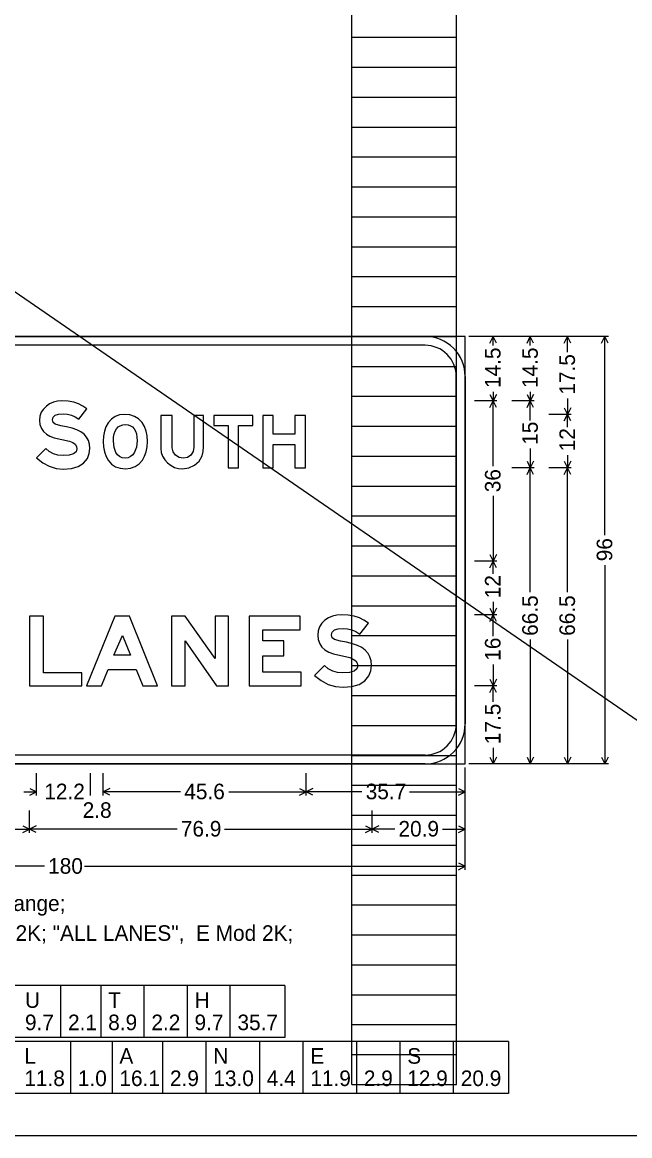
# Model space of a CAD drawing. Extents: x 1820207 to 1820557, y 740216 to 740315.
# Drawn here: x 1820495.55 to 1820501.23, y 740293.6 to 740304.02 of the extents above; entities that cross this region are included whole.
import ezdxf

# ---------------------------------------------------------------- set-up
doc = ezdxf.new("R2010")
doc.units = 0
for name, color, linetype in [('SC_Scratch1', 7, 'Continuous'), ('SC_Scratch2', 7, 'Continuous'), ('SC_Scratch3', 7, 'Continuous'), ('SC_Shading1', 7, 'Continuous')]:
    doc.layers.add(name, color=color, linetype=linetype)

msp = doc.modelspace()

# ---------------------------------------------------------------- linework, layer by layer
at = {"layer": 'SC_Scratch1'}
for p, q in [((1820498.631, 740294.081), (1820498.631, 740314.241)), ((1820499.611, 740294.081), (1820499.611, 740314.241)), ((1820498.631, 740303.881), (1820499.611, 740303.881)), ((1820498.631, 740303.601), (1820499.611, 740303.601)), ((1820498.631, 740303.321), (1820499.611, 740303.321)), ((1820498.631, 740303.041), (1820499.611, 740303.041)), ((1820498.631, 740302.761), (1820499.611, 740302.761)), ((1820498.631, 740302.481), (1820499.611, 740302.481)), ((1820498.631, 740302.201), (1820499.611, 740302.201)), ((1820498.631, 740301.921), (1820499.611, 740301.921)), ((1820498.631, 740301.641), (1820499.611, 740301.641)), ((1820498.631, 740301.361), (1820499.611, 740301.361)), ((1820498.631, 740301.081), (1820499.611, 740301.081)), ((1820498.631, 740300.801), (1820499.611, 740300.801)), ((1820498.631, 740300.521), (1820499.611, 740300.521)), ((1820498.631, 740300.241), (1820499.611, 740300.241)), ((1820498.631, 740299.961), (1820499.611, 740299.961)), ((1820498.631, 740299.681), (1820499.611, 740299.681)), ((1820498.631, 740299.401), (1820499.611, 740299.401)), ((1820498.631, 740299.121), (1820499.611, 740299.121)), ((1820498.631, 740298.841), (1820499.611, 740298.841)), ((1820498.631, 740298.561), (1820499.611, 740298.561)), ((1820498.631, 740298.281), (1820499.611, 740298.281)), ((1820498.631, 740298.001), (1820499.611, 740298.001)), ((1820498.631, 740297.721), (1820499.611, 740297.721)), ((1820498.631, 740297.441), (1820499.611, 740297.441)), ((1820498.631, 740297.161), (1820499.611, 740297.161)), ((1820498.631, 740296.881), (1820499.611, 740296.881)), ((1820498.631, 740296.601), (1820499.611, 740296.601)), ((1820498.631, 740296.321), (1820499.611, 740296.321)), ((1820498.631, 740296.041), (1820499.611, 740296.041)), ((1820498.631, 740295.761), (1820499.611, 740295.761)), ((1820498.631, 740295.481), (1820499.611, 740295.481)), ((1820498.631, 740295.201), (1820499.611, 740295.201)), ((1820498.631, 740294.921), (1820499.611, 740294.921)), ((1820498.631, 740294.641), (1820499.611, 740294.641)), ((1820498.631, 740294.361), (1820499.611, 740294.361)), ((1820498.631, 740294.081), (1820499.611, 740294.081))]:
    msp.add_line(p, q, dxfattribs=at)
at = {"layer": 'SC_Scratch2'}
msp.add_lwpolyline([(1820476.451, 740314.601), (1820506.951, 740314.601), (1820506.951, 740293.601), (1820476.451, 740293.601)], close=True, dxfattribs=at)
at = {"layer": 'SC_Scratch3'}
for p, q in [((1820501.033, 740301.081), (1820499.726, 740301.081)), ((1820499.987, 740301.081), (1820499.778, 740301.081)), ((1820499.921, 740301.019), (1820499.952, 740301.081)), ((1820499.952, 740300.995), (1820499.952, 740301.081)), ((1820499.984, 740301.019), (1820499.952, 740301.081)), ((1820500.336, 740301.081), (1820500.127, 740301.081)), ((1820500.27, 740301.019), (1820500.301, 740301.081)), ((1820500.301, 740300.995), (1820500.301, 740301.081)), ((1820500.332, 740301.019), (1820500.301, 740301.081)), ((1820500.684, 740301.081), (1820500.475, 740301.081)), ((1820500.618, 740301.019), (1820500.65, 740301.081)), ((1820500.65, 740300.933), (1820500.65, 740301.081)), ((1820500.681, 740301.019), (1820500.65, 740301.081)), ((1820500.967, 740301.019), (1820500.998, 740301.081)), ((1820500.998, 740299.22), (1820500.998, 740301.081)), ((1820501.029, 740301.019), (1820500.998, 740301.081)), ((1820499.987, 740300.477), (1820499.778, 740300.477)), ((1820499.921, 740300.539), (1820499.952, 740300.477)), ((1820499.921, 740300.415), (1820499.952, 740300.477)), ((1820499.952, 740300.563), (1820499.952, 740300.477)), ((1820499.984, 740300.539), (1820499.952, 740300.477)), ((1820499.952, 740299.866), (1820499.952, 740300.477)), ((1820499.984, 740300.415), (1820499.952, 740300.477)), ((1820500.336, 740300.477), (1820500.127, 740300.477)), ((1820500.27, 740300.539), (1820500.301, 740300.477)), ((1820500.27, 740300.415), (1820500.301, 740300.477)), ((1820500.301, 740300.563), (1820500.301, 740300.477)), ((1820500.332, 740300.539), (1820500.301, 740300.477)), ((1820500.301, 740300.296), (1820500.301, 740300.477)), ((1820500.332, 740300.415), (1820500.301, 740300.477)), ((1820500.65, 740300.501), (1820500.65, 740300.352)), ((1820500.618, 740300.414), (1820500.65, 740300.352)), ((1820500.681, 740300.414), (1820500.65, 740300.352)), ((1820500.684, 740300.352), (1820500.475, 740300.352)), ((1820500.618, 740300.29), (1820500.65, 740300.352)), ((1820500.65, 740300.233), (1820500.65, 740300.352)), ((1820500.681, 740300.29), (1820500.65, 740300.352)), ((1820500.301, 740300.033), (1820500.301, 740299.852)), ((1820500.65, 740299.971), (1820500.65, 740299.852)), ((1820500.336, 740299.852), (1820500.127, 740299.852)), ((1820500.336, 740299.852), (1820500.127, 740299.852)), ((1820500.27, 740299.914), (1820500.301, 740299.852)), ((1820500.27, 740299.79), (1820500.301, 740299.852)), ((1820500.332, 740299.914), (1820500.301, 740299.852)), ((1820500.301, 740298.689), (1820500.301, 740299.852)), ((1820500.332, 740299.79), (1820500.301, 740299.852)), ((1820500.684, 740299.852), (1820500.475, 740299.852)), ((1820500.684, 740299.852), (1820500.475, 740299.852)), ((1820500.618, 740299.914), (1820500.65, 740299.852)), ((1820500.618, 740299.79), (1820500.65, 740299.852)), ((1820500.681, 740299.914), (1820500.65, 740299.852)), ((1820500.65, 740298.689), (1820500.65, 740299.852)), ((1820500.681, 740299.79), (1820500.65, 740299.852)), ((1820499.952, 740299.588), (1820499.952, 740298.977)), ((1820499.921, 740299.039), (1820499.952, 740298.977)), ((1820499.984, 740299.039), (1820499.952, 740298.977)), ((1820499.987, 740298.977), (1820499.778, 740298.977)), ((1820499.921, 740298.915), (1820499.952, 740298.977)), ((1820499.952, 740298.858), (1820499.952, 740298.977)), ((1820499.984, 740298.915), (1820499.952, 740298.977)), ((1820500.998, 740298.942), (1820500.998, 740297.081)), ((1820499.952, 740298.596), (1820499.952, 740298.477)), ((1820499.921, 740298.539), (1820499.952, 740298.477)), ((1820499.984, 740298.539), (1820499.952, 740298.477)), ((1820499.987, 740298.477), (1820499.778, 740298.477)), ((1820499.921, 740298.415), (1820499.952, 740298.477)), ((1820499.952, 740298.276), (1820499.952, 740298.477)), ((1820499.984, 740298.415), (1820499.952, 740298.477)), ((1820500.301, 740298.244), (1820500.301, 740297.081)), ((1820500.65, 740298.244), (1820500.65, 740297.081)), ((1820499.952, 740298.011), (1820499.952, 740297.81)), ((1820499.921, 740297.873), (1820499.952, 740297.81)), ((1820499.984, 740297.873), (1820499.952, 740297.81)), ((1820499.987, 740297.81), (1820499.778, 740297.81)), ((1820499.987, 740297.81), (1820499.778, 740297.81)), ((1820499.921, 740297.748), (1820499.952, 740297.81)), ((1820499.952, 740297.662), (1820499.952, 740297.81)), ((1820499.984, 740297.748), (1820499.952, 740297.81)), ((1820499.921, 740297.144), (1820499.952, 740297.081)), ((1820499.952, 740297.23), (1820499.952, 740297.081)), ((1820499.984, 740297.144), (1820499.952, 740297.081)), ((1820500.27, 740297.144), (1820500.301, 740297.081)), ((1820500.332, 740297.144), (1820500.301, 740297.081)), ((1820500.618, 740297.144), (1820500.65, 740297.081)), ((1820500.681, 740297.144), (1820500.65, 740297.081)), ((1820500.967, 740297.144), (1820500.998, 740297.081)), ((1820501.029, 740297.144), (1820500.998, 740297.081)), ((1820499.691, 740296.088), (1820499.691, 740297.046)), ((1820501.033, 740297.081), (1820499.726, 740297.081)), ((1820499.987, 740297.081), (1820499.778, 740297.081)), ((1820500.336, 740297.081), (1820500.127, 740297.081)), ((1820500.684, 740297.081), (1820500.475, 740297.081)), ((1820495.679, 740296.785), (1820495.679, 740296.994)), ((1820496.185, 740296.785), (1820496.185, 740296.994)), ((1820496.303, 740296.785), (1820496.303, 740296.994)), ((1820498.203, 740296.785), (1820498.203, 740296.994)), ((1820498.203, 740296.785), (1820498.203, 740296.994)), ((1820499.691, 740296.785), (1820499.691, 740296.994)), ((1820495.56, 740296.82), (1820495.679, 740296.82)), ((1820495.616, 740296.851), (1820495.679, 740296.82)), ((1820495.616, 740296.789), (1820495.679, 740296.82)), ((1820496.365, 740296.851), (1820496.303, 740296.82)), ((1820497.027, 740296.82), (1820496.303, 740296.82)), ((1820496.365, 740296.789), (1820496.303, 740296.82)), ((1820497.479, 740296.82), (1820498.203, 740296.82)), ((1820498.141, 740296.851), (1820498.203, 740296.82)), ((1820498.141, 740296.789), (1820498.203, 740296.82)), ((1820498.265, 740296.851), (1820498.203, 740296.82)), ((1820498.725, 740296.82), (1820498.203, 740296.82)), ((1820498.265, 740296.789), (1820498.203, 740296.82)), ((1820499.169, 740296.82), (1820499.691, 740296.82)), ((1820499.629, 740296.851), (1820499.691, 740296.82)), ((1820499.629, 740296.789), (1820499.691, 740296.82)), ((1820495.614, 740296.436), (1820495.614, 740296.645)), ((1820498.821, 740296.436), (1820498.821, 740296.645)), ((1820498.821, 740296.436), (1820498.821, 740296.645)), ((1820499.691, 740296.436), (1820499.691, 740296.645)), ((1820495.414, 740296.471), (1820495.614, 740296.471)), ((1820495.552, 740296.502), (1820495.614, 740296.471)), ((1820495.552, 740296.44), (1820495.614, 740296.471)), ((1820495.677, 740296.502), (1820495.614, 740296.471)), ((1820496.995, 740296.471), (1820495.614, 740296.471)), ((1820495.677, 740296.44), (1820495.614, 740296.471)), ((1820497.44, 740296.471), (1820498.821, 740296.471)), ((1820498.759, 740296.502), (1820498.821, 740296.471)), ((1820498.759, 740296.44), (1820498.821, 740296.471)), ((1820498.883, 740296.502), (1820498.821, 740296.471)), ((1820499.032, 740296.471), (1820498.821, 740296.471)), ((1820498.883, 740296.44), (1820498.821, 740296.471)), ((1820499.48, 740296.471), (1820499.691, 740296.471)), ((1820499.629, 740296.502), (1820499.691, 740296.471)), ((1820499.629, 740296.44), (1820499.691, 740296.471)), ((1820495.754, 740296.123), (1820492.191, 740296.123)), ((1820496.128, 740296.123), (1820499.691, 740296.123)), ((1820499.629, 740296.154), (1820499.691, 740296.123)), ((1820499.629, 740296.091), (1820499.691, 740296.123)), ((1820498.003, 740295.007), (1820492.191, 740295.007)), ((1820495.904, 740295.007), (1820495.904, 740294.519)), ((1820496.281, 740295.007), (1820496.281, 740294.519)), ((1820496.684, 740295.007), (1820496.684, 740294.519)), ((1820497.088, 740295.007), (1820497.088, 740294.519)), ((1820497.49, 740295.007), (1820497.49, 740294.519)), ((1820498.003, 740295.007), (1820498.003, 740294.519)), ((1820498.003, 740294.519), (1820492.191, 740294.519)), ((1820500.097, 740294.484), (1820492.191, 740294.484)), ((1820495.997, 740294.484), (1820495.997, 740293.996)), ((1820496.386, 740294.484), (1820496.386, 740293.996)), ((1820496.859, 740294.484), (1820496.859, 740293.996)), ((1820497.264, 740294.484), (1820497.264, 740293.996)), ((1820497.765, 740294.484), (1820497.765, 740293.996)), ((1820498.172, 740294.484), (1820498.172, 740293.996)), ((1820498.674, 740294.484), (1820498.674, 740293.996)), ((1820499.079, 740294.484), (1820499.079, 740293.996)), ((1820499.58, 740294.484), (1820499.58, 740293.996)), ((1820500.097, 740294.484), (1820500.097, 740293.996)), ((1820500.097, 740293.996), (1820492.191, 740293.996))]:
    msp.add_line(p, q, dxfattribs=at)
for points in [[(1820492.191, 740297.081), (1820499.691, 740297.081), (1820499.691, 740301.081), (1820492.191, 740301.081), (1820492.191, 740297.081), (1820492.191, 740297.081), (1820492.191, 740297.081)], [(1820492.566, 740301.081), (1820499.316, 740301.081)], [(1820499.316, 740300.998), (1820492.566, 740300.998)], [(1820499.316, 740300.998), (1820499.316, 740300.998), (1820499.316, 740300.998)], [(1820499.608, 740297.456), (1820499.608, 740300.706)], [(1820499.691, 740300.706), (1820499.691, 740297.456)], [(1820499.608, 740297.456), (1820499.608, 740297.456), (1820499.608, 740297.456)], [(1820492.566, 740297.165), (1820499.316, 740297.165)], [(1820499.316, 740297.081), (1820492.566, 740297.081)]]:
    msp.add_lwpolyline(points, dxfattribs=at)
for points in [[(1820495.679, 740299.944), (1820495.737, 740299.899), (1820495.798, 740299.866), (1820495.863, 740299.846), (1820495.93, 740299.84), (1820496.007, 740299.846), (1820496.07, 740299.865), (1820496.12, 740299.896), (1820496.155, 740299.94), (1820496.173, 740299.985), (1820496.179, 740300.033), (1820496.176, 740300.072), (1820496.166, 740300.107), (1820496.148, 740300.138), (1820496.125, 740300.165), (1820496.094, 740300.188), (1820496.056, 740300.208), (1820496.012, 740300.223), (1820495.961, 740300.235), (1820495.906, 740300.243), (1820495.854, 740300.259), (1820495.835, 740300.276), (1820495.828, 740300.3), (1820495.835, 740300.325), (1820495.854, 740300.343), (1820495.886, 740300.353), (1820495.93, 740300.357), (1820495.969, 740300.354), (1820496.006, 740300.344), (1820496.041, 740300.329), (1820496.076, 740300.307), (1820496.151, 740300.403), (1820496.112, 740300.43), (1820496.073, 740300.45), (1820496.027, 740300.465), (1820495.975, 740300.474), (1820495.916, 740300.477), (1820495.875, 740300.474), (1820495.837, 740300.465), (1820495.802, 740300.45), (1820495.771, 740300.43), (1820495.743, 740300.402), (1820495.723, 740300.371), (1820495.711, 740300.335), (1820495.707, 740300.296), (1820495.711, 740300.258), (1820495.726, 740300.221), (1820495.745, 740300.192), (1820495.771, 740300.168), (1820495.804, 740300.149), (1820495.844, 740300.133), (1820495.988, 740300.1), (1820496.019, 740300.088), (1820496.041, 740300.072), (1820496.054, 740300.052), (1820496.058, 740300.029), (1820496.05, 740300.001), (1820496.025, 740299.982), (1820495.985, 740299.97), (1820495.927, 740299.966), (1820495.88, 740299.97), (1820495.838, 740299.983), (1820495.799, 740300.003), (1820495.765, 740300.032)], [(1820496.719, 740300.099), (1820496.715, 740300.15), (1820496.706, 740300.196), (1820496.689, 740300.238), (1820496.667, 740300.275), (1820496.635, 740300.309), (1820496.597, 740300.333), (1820496.553, 740300.347), (1820496.504, 740300.352), (1820496.457, 740300.347), (1820496.416, 740300.332), (1820496.38, 740300.307), (1820496.35, 740300.272), (1820496.329, 740300.235), (1820496.315, 740300.194), (1820496.306, 740300.149), (1820496.303, 740300.099), (1820496.306, 740300.048), (1820496.315, 740300.001), (1820496.33, 740299.959), (1820496.351, 740299.922), (1820496.382, 740299.887), (1820496.419, 740299.862), (1820496.462, 740299.847), (1820496.511, 740299.842), (1820496.56, 740299.847), (1820496.603, 740299.863), (1820496.639, 740299.888), (1820496.67, 740299.923), (1820496.691, 740299.96), (1820496.706, 740300.002), (1820496.715, 740300.048)], [(1820497.243, 740300.051), (1820497.243, 740300.342), (1820497.151, 740300.342), (1820497.151, 740300.044), (1820497.144, 740300.003), (1820497.124, 740299.971), (1820497.092, 740299.949), (1820497.053, 740299.942), (1820497.015, 740299.949), (1820496.981, 740299.971), (1820496.957, 740300.002), (1820496.949, 740300.039), (1820496.949, 740300.342), (1820496.843, 740300.342), (1820496.843, 740300.032), (1820496.847, 740299.995), (1820496.859, 740299.96), (1820496.879, 740299.927), (1820496.906, 740299.897), (1820496.938, 740299.873), (1820496.972, 740299.856), (1820497.009, 740299.846), (1820497.047, 740299.842), (1820497.105, 740299.851), (1820497.157, 740299.876), (1820497.2, 740299.915), (1820497.229, 740299.965), (1820497.24, 740300.003)], [(1820497.474, 740299.852), (1820497.569, 740299.852), (1820497.569, 740300.248), (1820497.704, 740300.248), (1820497.704, 740300.342), (1820497.338, 740300.342), (1820497.338, 740300.248), (1820497.474, 740300.248)], [(1820497.798, 740299.852), (1820497.894, 740299.852), (1820497.894, 740300.069), (1820498.096, 740300.069), (1820498.096, 740299.852), (1820498.198, 740299.852), (1820498.198, 740300.342), (1820498.096, 740300.342), (1820498.096, 740300.167), (1820497.894, 740300.167), (1820497.894, 740300.342), (1820497.798, 740300.342)], [(1820496.62, 740300.103), (1820496.615, 740300.045), (1820496.597, 740299.997), (1820496.581, 740299.974), (1820496.56, 740299.957), (1820496.536, 740299.946), (1820496.509, 740299.943), (1820496.481, 740299.946), (1820496.457, 740299.956), (1820496.436, 740299.973), (1820496.42, 740299.996), (1820496.405, 740300.042), (1820496.399, 740300.101), (1820496.401, 740300.137), (1820496.406, 740300.169), (1820496.415, 740300.195), (1820496.428, 740300.217), (1820496.444, 740300.234), (1820496.463, 740300.246), (1820496.486, 740300.253), (1820496.513, 740300.256), (1820496.538, 740300.254), (1820496.56, 740300.246), (1820496.578, 740300.234), (1820496.594, 740300.218), (1820496.605, 740300.196), (1820496.614, 740300.17), (1820496.619, 740300.139)], [(1820495.614, 740297.81), (1820496.102, 740297.81), (1820496.102, 740297.933), (1820495.743, 740297.933), (1820495.743, 740298.464), (1820495.614, 740298.464)], [(1820496.148, 740297.81), (1820496.288, 740297.81), (1820496.35, 740297.965), (1820496.611, 740297.965), (1820496.673, 740297.81), (1820496.813, 740297.81), (1820496.548, 740298.464), (1820496.413, 740298.464)], [(1820496.941, 740297.81), (1820497.069, 740297.81), (1820497.069, 740298.234), (1820497.363, 740297.81), (1820497.475, 740297.81), (1820497.475, 740298.464), (1820497.351, 740298.464), (1820497.351, 740298.068), (1820497.069, 740298.464), (1820496.941, 740298.464)], [(1820498.156, 740297.939), (1820497.796, 740297.939), (1820497.796, 740298.092), (1820497.995, 740298.092), (1820497.995, 740298.233), (1820497.796, 740298.233), (1820497.796, 740298.336), (1820498.146, 740298.336), (1820498.146, 740298.464), (1820497.668, 740298.464), (1820497.668, 740297.81), (1820498.156, 740297.81)], [(1820498.281, 740297.909), (1820498.343, 740297.86), (1820498.408, 740297.825), (1820498.477, 740297.804), (1820498.549, 740297.798), (1820498.631, 740297.804), (1820498.699, 740297.824), (1820498.751, 740297.858), (1820498.789, 740297.905), (1820498.809, 740297.952), (1820498.815, 740298.003), (1820498.811, 740298.045), (1820498.8, 740298.082), (1820498.782, 740298.115), (1820498.756, 740298.144), (1820498.724, 740298.169), (1820498.684, 740298.19), (1820498.636, 740298.206), (1820498.582, 740298.219), (1820498.524, 740298.228), (1820498.468, 740298.244), (1820498.447, 740298.262), (1820498.441, 740298.289), (1820498.447, 740298.315), (1820498.468, 740298.334), (1820498.502, 740298.345), (1820498.549, 740298.349), (1820498.59, 740298.346), (1820498.63, 740298.336), (1820498.668, 740298.319), (1820498.704, 740298.295), (1820498.785, 740298.398), (1820498.743, 740298.427), (1820498.702, 740298.449), (1820498.653, 740298.464), (1820498.597, 740298.474), (1820498.534, 740298.477), (1820498.49, 740298.474), (1820498.45, 740298.464), (1820498.413, 740298.449), (1820498.379, 740298.426), (1820498.349, 740298.397), (1820498.328, 740298.364), (1820498.315, 740298.326), (1820498.311, 740298.284), (1820498.316, 740298.244), (1820498.331, 740298.204), (1820498.351, 740298.173), (1820498.379, 740298.148), (1820498.415, 740298.127), (1820498.458, 740298.111), (1820498.611, 740298.075), (1820498.644, 740298.062), (1820498.667, 740298.045), (1820498.681, 740298.024), (1820498.686, 740297.999), (1820498.677, 740297.97), (1820498.651, 740297.949), (1820498.607, 740297.936), (1820498.546, 740297.932), (1820498.496, 740297.936), (1820498.451, 740297.95), (1820498.41, 740297.971), (1820498.373, 740298.002)], [(1820496.403, 740298.097), (1820496.484, 740298.282), (1820496.558, 740298.097)]]:
    msp.add_lwpolyline(points, close=True, dxfattribs=at)
for centre, radius, start, end in [((1820499.316, 740300.706), 0.375, 0, 90.0002), ((1820499.316, 740300.706), 0.292, 0, 90.0002), ((1820499.316, 740297.456), 0.375, 270.0001, 0.0003), ((1820499.316, 740297.456), 0.292, 270.0001, 0.0003)]:
    msp.add_arc(centre, radius, start, end, dxfattribs=at)
at = {"layer": 'SC_Shading1'}
msp.add_lwpolyline([(1820476.451, 740314.601), (1820506.951, 740293.601)], dxfattribs=at)

# ---------------------------------------------------------------- texts
at = {"layer": 'SC_Scratch3'}
for s, p in [('14.5', (1820500.022, 740300.598)), ('14.5', (1820500.371, 740300.598)), ('17.5', (1820500.719, 740300.536)), ('15', (1820500.371, 740300.067)), ('12', (1820500.719, 740300.006)), ('36', (1820500.022, 740299.623)), ('96', (1820501.068, 740298.977)), ('12', (1820500.022, 740298.631)), ('66.5', (1820500.371, 740298.279)), ('66.5', (1820500.719, 740298.279)), ('16', (1820500.022, 740298.046)), ('17.5', (1820500.022, 740297.265))]:
    msp.add_text(s, height=0.1458, rotation=90.0002, dxfattribs=at).set_placement(p)
for s, height, p in [('12.2', 0.1458, (1820495.752, 740296.75)), ('45.6', 0.1458, (1820497.062, 740296.75)), ('35.7', 0.1458, (1820498.76, 740296.75)), ('2.8', 0.1458, (1820496.111, 740296.576)), ('76.9', 0.1458, (1820497.03, 740296.401)), ('20.9', 0.1458, (1820499.067, 740296.401)), ('180', 0.1458, (1820495.788, 740296.053)), ('9.0" Radius, 2.0" Border, Black on, Orange;', 0.14583, (1820492.191, 740295.704)), ('Interstate 77 M1-1; "SOUTH",  E Mod 2K; "ALL LANES",  E Mod 2K;', 0.14583, (1820492.191, 740295.425)), ('U', 0.146, (1820495.571, 740294.798)), ('T', 0.146, (1820496.35, 740294.798)), ('H', 0.146, (1820497.158, 740294.798)), ('9.7', 0.1458, (1820495.571, 740294.589)), ('2.1', 0.1458, (1820495.974, 740294.589)), ('8.9', 0.1458, (1820496.35, 740294.589)), ('2.2', 0.1458, (1820496.754, 740294.589)), ('9.7', 0.1458, (1820497.158, 740294.589)), ('35.7', 0.1458, (1820497.56, 740294.589)), ('S', 0.146, (1820499.149, 740294.275)), ('L', 0.146, (1820495.565, 740294.275)), ('A', 0.146, (1820496.455, 740294.275)), ('N', 0.146, (1820497.334, 740294.275)), ('E', 0.146, (1820498.242, 740294.275)), ('11.8', 0.1458, (1820495.565, 740294.066)), ('1.0', 0.1458, (1820496.066, 740294.066)), ('16.1', 0.1458, (1820496.455, 740294.066)), ('2.9', 0.1458, (1820496.928, 740294.066)), ('13.0', 0.1458, (1820497.334, 740294.066)), ('4.4', 0.1458, (1820497.834, 740294.066)), ('11.9', 0.1458, (1820498.242, 740294.066)), ('2.9', 0.1458, (1820498.743, 740294.066)), ('12.9', 0.1458, (1820499.149, 740294.066)), ('20.9', 0.1458, (1820499.65, 740294.066))]:
    msp.add_text(s, height=height, dxfattribs=at).set_placement(p)

doc.saveas('drawing.dxf')
